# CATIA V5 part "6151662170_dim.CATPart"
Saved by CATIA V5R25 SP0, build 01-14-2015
Part number: 6151662170_dim
Source: made
Property "PROI_CREATED_ON": "12/17/2008 9:21:37 AM"
Property "BLANK_DRAWING": "--"
Property "DRAWN_BY": "VGU"
Property "FINISH": "--"
Property "HEAT_TREATMENT": "ASSIGN"
Property "MATERIAL": "ASSIGN"
Property "PROJECT": "--"
Property "PROTOTYPE_NO": "--"
Property "RELATED_DRAWING": "--"
Property "COMPLETE_MATERIAL": "ASSIGN-ASSIGN"
Property "DESCRIPTION": "EFD106-1100"
Property "DRAWING_EXIST": "--"
Property "MANUFACTURER": "--"
Property "MANUFACTURER_2": "--"
Property "MANUFACTURER_REF": "--"
Property "TYPE_PART": "--"
Property "TODAY_DATE": "2022/03/28"
Property "PDMREV": "02.0"
Property "PDMRL": "Production"
Property "PROI_REVISION": "02"
Property "PROI_VERSION": "0"
Property "PROI_RELEASE": "Production"
Property "PTC_MODIFIED": false
Property "MFG_WP_MATERIAL": "ASSIGN"
Property "COMPANY_CODE": "---"
Property "DESCRIPTION_JP": "--"
Property "PQP_DOCUMENT": "--"
Property "GHOST": false
Property "NO_PART": false
Property "PTC_WM_ITERATION": "0"
Property "PTC_WM_VERSION": "02.0"
Property "PTC_WM_CREATED_ON": "09-Aug-23 09:43:59 AM"
Property "PTC_WM_MODIFIED_ON": "09-Aug-23 09:44:00 AM"
Property "PTC_WM_NAME": "6151662170_dim.prt"
Property "PTC_WM_NUMBER": "6151662170_DIM.PRT"
Property "PTC_WM_LIFECYCLE_STATE": "Production"
Property "PTC_WM_LIFECYCLE": "Design_Process"
Property "PTC_WM_REVISION": "02"
Property "PTC_WM_CREATED_BY": "Florian Pavageau (Grefpav) (Grefpav: CPD)"
Property "PTC_WM_MODIFIED_BY": "Florian Pavageau (Grefpav) (Grefpav: CPD)"
Property "PTC_ORGANIZATION_ID": "CPD"
Property "PTC_WM_LOCATION": "/Products/ELECTRIC EB TOOLS/A2080 - EFx GEN2/9-01-Dimensional Drawings and 3D"
Property "PTC_WM_PART_NAME": "6151662170_dim.prt"
Property "PTC_WM_PART_NUMBER": "6151662170_DIM"
Property "PTC_WM_TEAM": "Default"
Property "EXPORT_CONTROL": "NULL"
Property "PTC_COMMON_NAME": "6151662170_dim.prt"
Property "PTC_MASTER_MATERIAL": "ASSIGN"
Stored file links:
  d:\ptc\Echange\temp\6151662170_dim.CATPart

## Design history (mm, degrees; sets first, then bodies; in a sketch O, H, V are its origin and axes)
AxisSystem1 "CS0": origin (0, 0, 0), X (1, 0, 0), Y (0, 1, 0), Z (0, 0, 1)
Set1
  DatumSurface1 "Sheet.1"
  DatumSurface2 "Sheet.2"
  DatumSurface3 "Sheet.3"
  DatumSurface4 "Sheet.4"
  DatumSurface5 "Sheet.5"
  DatumSurface6 "Sheet.6"
  DatumSurface7 "Sheet.7"
  DatumSurface8 "Sheet.8"
  DatumSurface9 "Sheet.9"
  DatumSurface10 "Sheet.10"
  DatumSurface11 "Sheet.11"
  DatumSurface12 "Sheet.12"
  DatumSurface13 "Sheet.13"
  DatumSurface14 "Sheet.14"
  DatumSurface15 "Sheet.15"
  DatumSurface16 "Sheet.16"
  DatumSurface17 "Sheet.17"
  DatumSurface18 "Sheet.18"
  DatumSurface19 "Sheet.19"
  DatumSurface20 "Sheet.20"
  DatumSurface21 "Sheet.21"
  DatumSurface22 "Sheet.22"
  DatumSurface23 "Sheet.23"
  DatumSurface24 "Sheet.24"
  DatumSurface25 "Sheet.25"
  DatumSurface26 "Sheet.26"
  DatumSurface27 "Sheet.27"
  DatumSurface28 "Sheet.28"
  DatumSurface29 "Sheet.29"
  DatumSurface30 "Sheet.30"
  DatumSurface31 "Sheet.31"
  DatumSurface32 "Sheet.32"
  DatumSurface33 "Sheet.33"
  DatumSurface34 "Sheet.34"
  DatumSurface35 "Sheet.35"
  DatumSurface36 "Sheet.36"
  DatumSurface37 "Sheet.37"
  DatumSurface38 "Sheet.38"
  DatumSurface39 "Sheet.39"
  DatumSurface40 "Sheet.40"
  DatumSurface41 "Sheet.41"
  DatumSurface42 "Sheet.42"
  DatumSurface43 "Sheet.43"
  DatumSurface44 "Sheet.44"
  DatumSurface45 "Sheet.45"
  DatumSurface46 "Sheet.46"
  DatumSurface47 "Sheet.47"
  DatumSurface48 "Sheet.48"
  DatumSurface49 "Sheet.49"
  DatumSurface50 "Sheet.50"
  DatumSurface51 "Sheet.51"
  DatumSurface52 "Sheet.52"
  DatumSurface53 "Sheet.53"
  DatumSurface54 "Sheet.54"
  Plane1 "RIGHT": stored without definition
  Plane2 "TOP": stored without definition
  Plane3 "FRONT": stored without definition
Body1 "PartBody" (main body)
